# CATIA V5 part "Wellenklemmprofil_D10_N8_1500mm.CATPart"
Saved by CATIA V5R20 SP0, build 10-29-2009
Part number: Wellenklemmprofil_D10_N8_X-Achse
Bounding box of the stored display mesh (mm): x 0 to 1420, y -9 to 9, z -12 to 15
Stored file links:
  C:\Users\Andi\Desktop\Plasma\Wellenklemmprofil_D10_N8_1500mm.CATPart
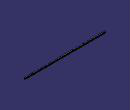
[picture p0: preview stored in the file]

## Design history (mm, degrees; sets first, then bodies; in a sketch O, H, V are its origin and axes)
Body1 (main body)
  Sketch1 on yz-plane, origin (0, 0, 0), H (0, 1, 0), V (0, 0, 1)
    line L1 (-9, 10) -> (-9, 0)
    point P2 (-9, 0)
    line L2 (-9, 0) -> (-4, 0)
    line L3 (-4, 0) -> (-4, -12)
    line L4 (-4, -12) -> (4, -12)
    line L5 (4, -12) -> (4, 0)
    point P6 (4, 0)
    line L6 (4, 0) -> (9, 0)
    line L7 (9, 0) -> (9, 10)
    line L8 (9, 10) -> (7.0993, 10)
    line L9 (-9, 10) -> (-7.0993, 10)
    arc A1 centre (0, 8) radius 7 from (-6.8075, 9.6301) to (6.8075, 9.6301) ccw
    point P9 (0, 8)
    arc A2 centre (-7.0993, 9.7) radius 0.3 from (-6.8075, 9.6301) to (-7.0993, 10) ccw
    arc A3 centre (7.0993, 9.7) radius 0.3 from (6.8075, 9.6301) to (7.0993, 10) cw
    radius A1 = 7
    distance L6 L8 = 10
    distance L7 L1 = 18
    radius A2 = 0.3
    radius A3 = 0.3 {= Sketch1.radius(A2)}
    distance P9 L6 = 8
    distance L8 L4 = 22
    distance L5 L3 = 8
    coincidence: P2 H, P6 H, P9 V, L9 L8
    vertical: L1 V, L3 V, L5 V, L7 V
    horizontal: L2 H, L4 H, L6 H, L8 H, L9 H
    symmetry: L7 L1 V, L3 L5 V
    tangency: A2 A1, A2 L9, A3 A1, A3 L8
  Pad1: profile Sketch1, direction (1, 0, 0), length 1420
  Fillet1: radius 0.3, on edge [face of Pad1 from Sketch1.L8 | face of Pad1 from Sketch1.L7]; edge [face of Pad1 from Sketch1.L1 | face of Pad1 from Sketch1.L9]
Body2
  Sketch2 on yz-plane, origin (0, 0, 0), H (0, 1, 0), V (0, 0, 1)
    circle A1 centre (0, 8) radius 7
    reference projected arc E1 centre (0, 8) radius 7 from (-6.8182, 9.5849) to (6.8182, 9.5849) ccw from edge [face of Pad1 from Sketch1.A1 | end face of Pad1]
    coincidence: A1 E1
  Pad2: profile Sketch2, direction (1, 0, 0), length 1420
